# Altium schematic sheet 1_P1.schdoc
size 309 x 223 mm; Symbol: Sheet-Symbol_A4; Device: Sheet-Symbol_A4; Company: 嘉立创EDA; Version: V1.0; Page Size: A4; @Project Name: 自制ev3触碰传感器; @Page Count: 1; @Update Date: 2024-11-17; @Create Date: 2024-11-17; @Schematic Name: Schematic1; @Page No: 1; @Page Name: P1; @Board Name: Board1; @Create Time: 00:27:39; @Update Time: 00:27:39
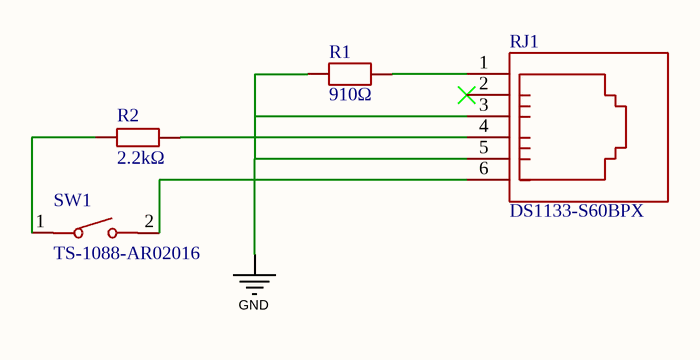
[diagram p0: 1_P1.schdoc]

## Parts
R1  910Ω  [R0805]  (value not drawn)
R2  2.2kΩ  [R0805]  (value not drawn)
RJ1  DS1133-S60BPX  [RJ11-TH_DS1133-S60BPX]  (value not drawn)
SW1  TS-1088-AR02016  [SW-SMD_L3.9-W3.0-P4.45]  (value not drawn)

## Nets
GND: R1.1 RJ1.3 RJ1.5
NetR1_2: R1.2 RJ1.1
NetR2_1: R2.1 SW1.1
NetR2_2: R2.2 RJ1.4
NetRJ1_6: RJ1.6 SW1.2

Not connected (* = marked no-connect by the designer): RJ1 2*

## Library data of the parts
R1 = FRC0805F9100TS: 电阻类型:厚膜电阻;阻值:910Ω;精度:±1%;功率:125mW;最大工作电压:150V;温度系数:±100ppm/℃;; Manufacturer: FOJAN(富捷); Add into BOM: yes; Tolerance: ±1%; Power(Watts): 125mW; Overload Voltage (Max): 150V
R2 = 0805W8F2201T5E: 电阻类型:厚膜电阻;阻值:2.2kΩ;精度:±1%;功率:125mW;最大工作电压:150V;温度系数:±100ppm/℃;; Manufacturer: UNI-ROYAL(厚声); Add into BOM: yes; Tolerance: ±1%; Power(Watts): 125mW; Overload Voltage (Max): 150V
RJ1 = DS1133-S60BPX: 连接器类型:RJ12插座;端口数量:1;屏蔽:-;LED:-;等级:-;; Manufacturer: CONNFLY; Add into BOM: yes; Connector Type: RJ12插座; Number of Ports: 1
SW1 = TS-1088-AR02016: 电路结构:单刀单掷;按钮形状:圆形按钮;作用力:160gf;安装方式:立贴;开关长度:4mm;开关宽度:3mm;开关高度:2mm;带支架:不带;触点电流:50mA;额定电压(DC):12V;绝缘电阻:100MΩ;机械寿命:10万次;; Manufacturer: XUNPU(讯普); Add into BOM: yes; Circuit: 单刀单掷; Actuator Style: 圆形按钮; Operating Force: 160gf; Switch Length: 4mm; Switch Width: 3mm; Switch Height: 2mm; Strike Gundam: 不带; Contact Current: 50mA; Voltage Rating (DC): 12V; Insulation Resistance: 100MΩ; Actuator/Cap Color: 黑色; Pin Style: SMD接片; Mechanical Life: 10万次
